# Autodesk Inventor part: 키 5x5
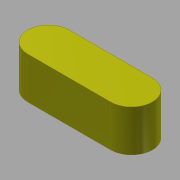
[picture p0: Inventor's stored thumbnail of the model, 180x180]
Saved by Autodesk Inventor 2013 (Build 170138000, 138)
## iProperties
Created: 2011-04
Part Number: 키 5x5
Document SubType Name: Modeling
Designer: pww
Density: 7.86 g/cm^3
Material: 강철, 연강
Author: pww
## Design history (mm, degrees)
sketch "스케치1"
  geometry: L1 (-5, -2.5)-(5, -2.5); L2 (5, 2.5)-(-5, 2.5); A1 r 2.5 centre (-5, 0) between (-5, 2.5) and (-5, -2.5); A2 r 2.5 centre (5, 0) between (5, -2.5) and (5, 2.5); 1 further point
  constraints: 4 end point, 4 point on circle, 2 centre point
extrude "돌출1" new body sketch "스케치1" distance "d0" = 5; taper "d1" = 0 deg
node "솔리드1"
